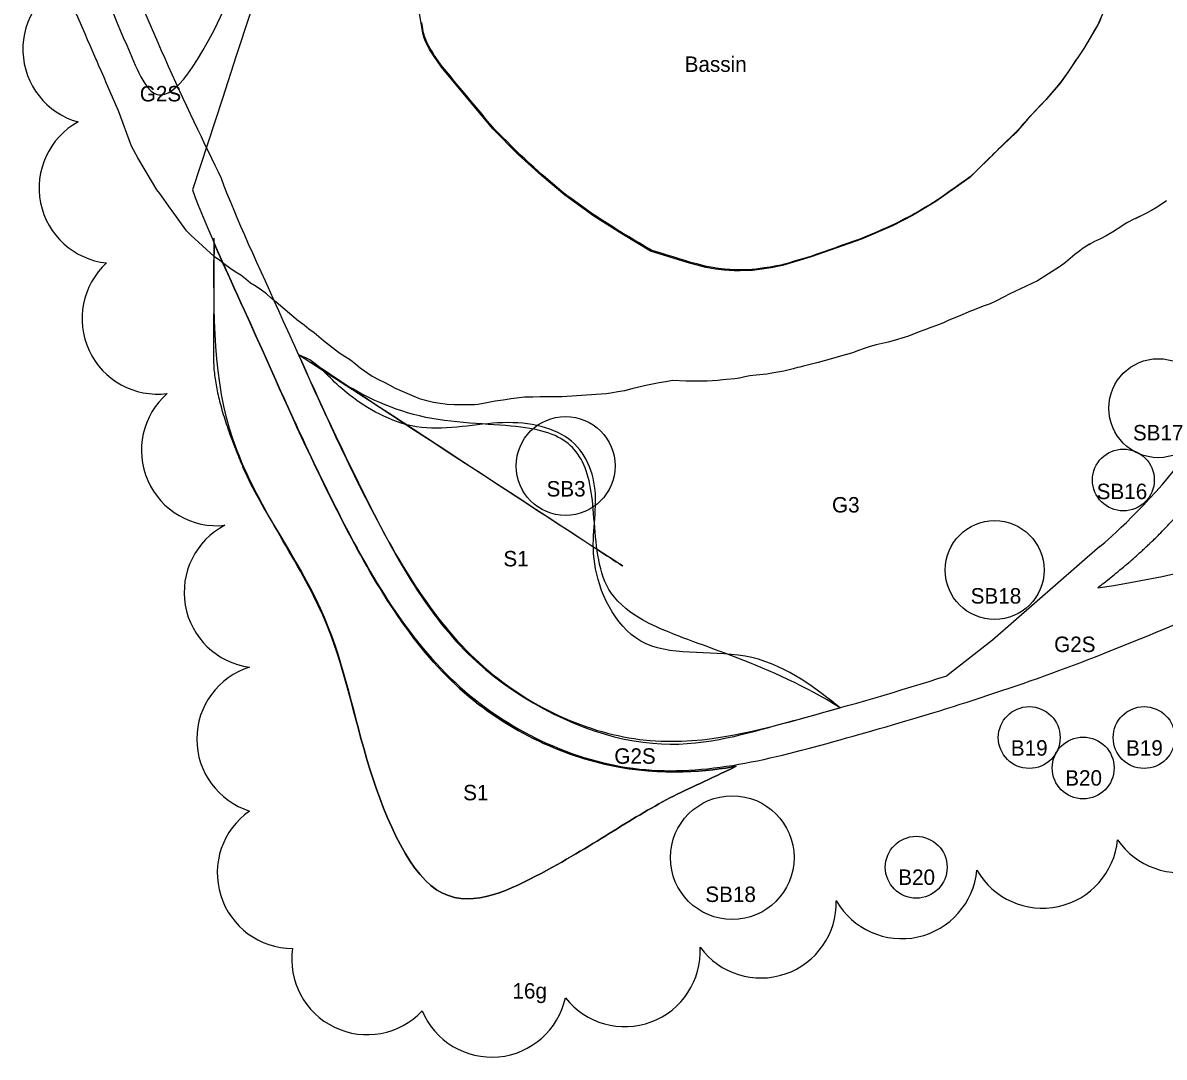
# Model space of a CAD drawing. Extents: x 0 to 512122, y 0 to 6212554.
# Drawn here: x 511409.2 to 511501.5, y 6211296 to 6211379.6 of the extents above; entities that cross this region are included whole.
import ezdxf

# ---------------------------------------------------------------- set-up
doc = ezdxf.new("R2010")
doc.units = 0
for name, color, linetype in [('_Paths', 7, 'Continuous'), ('_S1_rabarber', 7, 'Continuous'), ('Bassin - bottom', 7, 'Continuous'), ('Clouds', 7, 'Continuous'), ('TV_U_AFM_Symbl_Gul', 7, 'Continuous'), ('TV_U_LYS_Mastenummer', 7, 'Continuous'), ('TV_U_LYS_Nyx330-Trafiksti-x2', 7, 'Continuous')]:
    doc.layers.add(name, color=color, linetype=linetype)

msp = doc.modelspace()

# ---------------------------------------------------------------- linework, layer by layer
at = {"layer": '_Paths'}
msp.add_lwpolyline([(511496.345, 6211337.291), (511487.638, 6211329.704), (511483.951, 6211326.819)], dxfattribs=at)
msp.add_arc((511485.308, 6211411.031), 77.851, 278.00491, 309.13245, dxfattribs=at)
for points in [[(511450.039, 6211448.86), (511448.659, 6211442.81), (511441.758, 6211430.614), (511427.385, 6211422.182), (511415.868, 6211415.798), (511410.87, 6211405.413), (511411.537, 6211394.313), (511413.909, 6211386.762), (511418.057, 6211376.543), (511422.936, 6211366.106), (511450.039, 6211448.86), (511422.936, 6211366.106)], [(511452.493, 6211448.381), (511452.097, 6211446.356), (511450.738, 6211439.396), (511444.066, 6211426.759), (511429.553, 6211420.175), (511417.018, 6211415.504), (511412.404, 6211405.178), (511413.418, 6211395.795), (511416.522, 6211386.629), (511420.496, 6211376.909), (511423.945, 6211369.766), (511425.261, 6211367.041)], [(511496.284, 6211337.238), (511497.181, 6211337.983), (511503.211, 6211343.318), (511510.408, 6211356.244), (511526.967, 6211373.541), (511552.416, 6211374.723), (511569.62, 6211375.512), (511577.558, 6211375.876)], [(511496.15, 6211333.938), (511496.382, 6211334.119), (511496.614, 6211334.301), (511497.277, 6211334.827), (511497.707, 6211335.177), (511498.56, 6211335.891), (511498.983, 6211336.255), (511499.609, 6211336.816), (511499.816, 6211337.005), (511500.125, 6211337.293), (511500.227, 6211337.39), (511500.38, 6211337.535), (511500.431, 6211337.584), (511500.533, 6211337.682), (511500.583, 6211337.731), (511501.039, 6211338.174), (511501.432, 6211338.575), (511502.2, 6211339.389), (511502.574, 6211339.802), (511503.305, 6211340.639), (511503.662, 6211341.062), (511504.36, 6211341.916), (511504.702, 6211342.347), (511505.71, 6211343.65), (511506.356, 6211344.531), (511507.619, 6211346.304), (511508.235, 6211347.195), (511509.454, 6211348.976), (511510.058, 6211349.864), (511511.269, 6211351.627), (511511.876, 6211352.5), (511512.804, 6211353.79), (511513.115, 6211354.216), (511513.746, 6211355.061), (511514.065, 6211355.48), (511515.037, 6211356.725), (511515.702, 6211357.539), (511517.067, 6211359.122), (511517.767, 6211359.891), (511519.202, 6211361.371), (511519.937, 6211362.082), (511521.44, 6211363.435), (511522.209, 6211364.077), (511523.78, 6211365.279), (511524.583, 6211365.839), (511525.812, 6211366.612), (511526.226, 6211366.858), (511526.749, 6211367.15), (511526.853, 6211367.208), (511527.011, 6211367.293), (511527.064, 6211367.322), (511527.169, 6211367.378), (511527.222, 6211367.406), (511527.486, 6211367.545), (511527.7, 6211367.653), (511528.344, 6211367.971), (511528.781, 6211368.172), (511529.665, 6211368.555), (511530.114, 6211368.736), (511531.477, 6211369.251), (511532.41, 6211369.557), (511534.317, 6211370.104), (511535.292, 6211370.343), (511537.278, 6211370.766), (511538.289, 6211370.949), (511540.341, 6211371.267), (511541.381, 6211371.402), (511543.485, 6211371.635), (511544.548, 6211371.733), (511546.689, 6211371.901), (511547.767, 6211371.972), (511549.933, 6211372.096), (511551.02, 6211372.151), (511552.38, 6211372.215), (511552.652, 6211372.228), (511553.061, 6211372.247), (511553.197, 6211372.253), (511553.469, 6211372.266), (511553.605, 6211372.272), (511554.285, 6211372.304), (511555.913, 6211372.38), (511557.532, 6211372.455), (511560.757, 6211372.604), (511562.891, 6211372.704), (511566.075, 6211372.852), (511567.131, 6211372.901), (511568.185, 6211372.95)], [(511425.261, 6211367.041), (511426.423, 6211363.904), (511430.164, 6211355.897), (511436.319, 6211341.82), (511444.744, 6211326.863), (511459.39, 6211319.972), (511472.326, 6211323.351), (511480.124, 6211325.601), (511483.951, 6211326.819)], [(511422.936, 6211366.106), (511424.117, 6211362.932), (511427.915, 6211354.799), (511434.078, 6211340.703), (511442.957, 6211324.941), (511459.145, 6211317.324), (511475.029, 6211321.473), (511492.664, 6211326.687), (511505.824, 6211332.405), (511513.21, 6211335.68)]]:
    msp.add_open_spline(points, degree=3, dxfattribs=at)
at = {"layer": '_S1_rabarber'}
for points, degree in [([(511466.915, 6211319.511), (511464.697, 6211318.413), (511461.58, 6211317.119), (511456.737, 6211314.124), (511451.323, 6211310.773), (511442.088, 6211306.447), (511436.406, 6211320.592), (511434.43, 6211332.209), (511424.574, 6211345.595), (511424.646, 6211355.769), (511424.692, 6211362.215)], 3), ([(511424.689, 6211361.804), (511424.645, 6211355.496), (511424.652, 6211349.202), (511427.044, 6211343.62)], 2), ([(511424.689, 6211361.804), (511425.425, 6211360.117), (511428.531, 6211353.391), (511434.078, 6211340.703), (511442.957, 6211324.941), (511457.124, 6211318.275), (511464.776, 6211319.103), (511466.915, 6211319.511)], 3), ([(511466.915, 6211319.511), (511464.776, 6211319.103), (511457.124, 6211318.275), (511442.957, 6211324.941), (511434.078, 6211340.703), (511428.531, 6211353.391), (511425.425, 6211360.117), (511424.689, 6211361.804)], 3), ([(511475.316, 6211324.236), (511469.697, 6211327.763), (511457.957, 6211330.701), (511455.453, 6211335.54), (511455.453, 6211342.15), (511453.9, 6211345.823), (511449.929, 6211347.206), (511440.951, 6211347.206), (511434.131, 6211350.921), (511432.75, 6211352.217), (511431.512, 6211352.776), (511475.316, 6211324.236), (511431.512, 6211352.776)], 3), ([(511431.512, 6211352.776), (511433.015, 6211349.447), (511437.201, 6211340.255), (511444.745, 6211326.863), (511459.391, 6211319.971), (511469.457, 6211322.601), (511474.356, 6211323.965), (511475.316, 6211324.236)], 3), ([(511475.316, 6211324.236), (511473.557, 6211325.639), (511468.59, 6211329.599), (511458.65, 6211327.71), (511454.63, 6211335.987), (511456.066, 6211341.167), (511454.348, 6211346.436), (511448.167, 6211347.805), (511441.304, 6211346.051), (511435.366, 6211349.353), (511432.978, 6211352.237), (511431.944, 6211352.617), (511431.512, 6211352.776)], 3), ([(511431.512, 6211352.776), (511433.015, 6211349.447), (511437.201, 6211340.255), (511444.745, 6211326.863), (511459.391, 6211319.971), (511469.457, 6211322.601), (511474.356, 6211323.965), (511475.316, 6211324.236)], 3), ([(511427.044, 6211343.62), (511428.457, 6211340.321), (511434.43, 6211332.209), (511436.406, 6211320.592), (511442.088, 6211306.447), (511451.323, 6211310.773), (511456.737, 6211314.124), (511461.58, 6211317.119), (511464.697, 6211318.413), (511466.915, 6211319.511)], 3)]:
    msp.add_open_spline(points, degree=degree, dxfattribs=at)
at = {"layer": 'Bassin - bottom'}
msp.add_lwpolyline([(511497.036, 6211381.467), (511496.153, 6211379.46), (511495.031, 6211377.534), (511493.872, 6211375.818), (511493.14, 6211374.77), (511491.962, 6211373.383), (511490.531, 6211371.873), (511489.519, 6211370.719), (511488.027, 6211369.283), (511485.815, 6211367.1), (511483.052, 6211365.157), (511481.171, 6211364.036), (511479.554, 6211363.201), (511477.06, 6211362.117), (511472.976, 6211360.682), (511470.655, 6211359.988), (511469.755, 6211359.801), (511468.225, 6211359.601), (511467.226, 6211359.562), (511466.75, 6211359.562), (511465.946, 6211359.612), (511465.233, 6211359.699), (511464.45, 6211359.838), (511462.962, 6211360.229), (511459.99, 6211361.163), (511457.661, 6211362.549), (511455.393, 6211363.983), (511453.043, 6211365.671), (511451.184, 6211367.241), (511449.274, 6211368.974), (511447.234, 6211371.032), (511443.079, 6211376.016), (511442.477, 6211376.877), (511442.121, 6211377.457), (511441.834, 6211377.982), (511441.726, 6211378.244), (511441.648, 6211378.451), (511441.56, 6211378.805), (511441.157, 6211381.136)], dxfattribs=at)
at = {"layer": 'Clouds'}
for centre, radius, start, end in [((511415.323, 6211377.48), 6.1, 109.47776, 254.47776), ((511416.641, 6211366.262), 6.101, 118.92065, 263.92065), ((511420.11, 6211355.694), 6.1, 132.43503, 277.43503), ((511424.915, 6211345.053), 6.1, 131.15961, 276.15961), ((511428.37, 6211333.569), 6.1, 117.33555, 262.33555), ((511429.391, 6211321.706), 6.1, 107.5, 252.5), ((511502.794, 6211317.009), 6.1, 214.28131, 359.28131), ((511431.047, 6211310.885), 6.1, 124.89951, 269.89951), ((511491.679, 6211314.136), 6.1, 209.70863, 354.70863), ((511480.305, 6211311.67), 6.1, 209.76097, 354.76097), ((511468.912, 6211308.493), 6.1, 216.39722, 1.39722), ((511457.91, 6211304.553), 6.1, 218.00684, 3.00684), ((511437.073, 6211303.909), 6.1, 171.75121, 316.75121), ((511447.142, 6211302.09), 6.1, 202.76469, 347.76469)]:
    msp.add_arc(centre, radius, start, end, dxfattribs=at)
at = {"layer": 'TV_U_LYS_Mastenummer'}
for centre, radius in [((511501.05, 6211348.456), 4), ((511453.117, 6211343.786), 4), ((511498.228, 6211342.651), 2.5), ((511487.815, 6211335.372), 4), ((511490.611, 6211321.829), 2.5), ((511490.611, 6211321.829), 2.5), ((511499.901, 6211321.829), 2.5), ((511494.974, 6211319.369), 2.5), ((511494.974, 6211319.369), 2.5), ((511466.597, 6211312.12), 5), ((511466.597, 6211312.12), 5), ((511481.471, 6211311.344), 2.5), ((511481.471, 6211311.344), 2.5)]:
    msp.add_circle(centre, radius, dxfattribs=at)
at = {"layer": 'TV_U_LYS_Nyx330-Trafiksti-x2'}
for points in [[(511501.712, 6211365.222), (511501.049, 6211364.762), (511500.95, 6211364.706), (511500.509, 6211364.452), (511500.497, 6211364.446), (511500.029, 6211364.201), (511499.552, 6211363.964), (511499.199, 6211363.781), (511499.519, 6211363.947), (511499.199, 6211363.781), (511499.031, 6211363.71), (511499.009, 6211363.701), (511498.622, 6211363.5), (511498.557, 6211363.462), (511498.28, 6211363.298), (511498.19, 6211363.237), (511497.345, 6211362.679), (511497.291, 6211362.648), (511496.842, 6211362.394), (511496.374, 6211362.159), (511495.9, 6211361.93), (511495.455, 6211361.698), (511495.556, 6211361.755), (511495.494, 6211361.724), (511495.122, 6211361.483), (511494.965, 6211361.381), (511494.708, 6211361.19), (511494.304, 6211360.888), (511493.921, 6211360.564), (511493.54, 6211360.238), (511493.142, 6211359.93), (511493.065, 6211359.881), (511491.291, 6211358.749), (511490.832, 6211358.533), (511490.372, 6211358.317), (511489.912, 6211358.102), (511489.453, 6211357.886), (511488.996, 6211357.666), (511488.576, 6211357.452), (511487.903, 6211357.11), (511487.444, 6211356.904), (511486.968, 6211356.726), (511486.491, 6211356.55), (511486.019, 6211356.365), (511485.874, 6211356.302), (511485.049, 6211355.95), (511484.584, 6211355.76), (511484.123, 6211355.563), (511483.69, 6211355.362), (511483.116, 6211355.14), (511482.645, 6211354.97), (511482.174, 6211354.798), (511481.706, 6211354.621), (511481.24, 6211354.439), (511480.774, 6211354.257), (511480.59, 6211354.189), (511479.695, 6211353.924), (511479.207, 6211353.803), (511478.72, 6211353.683), (511478.231, 6211353.565), (511477.747, 6211353.433), (511477.268, 6211353.291), (511476.801, 6211353.111), (511476.332, 6211352.936), (511475.852, 6211352.794), (511475.828, 6211352.787), (511474.982, 6211352.558), (511474.502, 6211352.42), (511474.021, 6211352.282), (511473.537, 6211352.154), (511473.108, 6211352.031), (511472.364, 6211351.852), (511472.07, 6211351.783), (511471.877, 6211351.737), (511471.525, 6211351.631), (511470.771, 6211351.442), (511470.276, 6211351.37), (511469.784, 6211351.279), (511469.379, 6211351.215), (511468.523, 6211351.115), (511468.024, 6211351.064), (511467.618, 6211350.981), (511467.184, 6211350.893), (511466.799, 6211350.838), (511466.135, 6211350.781), (511465.846, 6211350.745), (511465.631, 6211350.718), (511465.439, 6211350.695), (511464.573, 6211350.646), (511464.16, 6211350.643), (511463.57, 6211350.637), (511463.063, 6211350.639), (511462.856, 6211350.639), (511461.772, 6211350.697), (511461.229, 6211350.599), (511460.686, 6211350.5), (511460.423, 6211350.452), (511459.601, 6211350.303), (511459.032, 6211350.162), (511458.462, 6211350.014), (511457.892, 6211349.868), (511457.338, 6211349.774), (511456.785, 6211349.681), (511456.388, 6211349.613), (511452.808, 6211349.368), (511452.225, 6211349.366), (511451.641, 6211349.363), (511451.058, 6211349.361), (511450.474, 6211349.359), (511449.891, 6211349.356), (511449.805, 6211349.345), (511448.712, 6211349.202), (511448.067, 6211349.118), (511447.423, 6211349.034), (511446.738, 6211348.886), (511446.057, 6211348.746), (511445.744, 6211348.72), (511444.121, 6211348.716), (511443.54, 6211348.764), (511443.383, 6211348.777), (511442.979, 6211348.84), (511442.425, 6211348.925), (511442.319, 6211348.942), (511441.899, 6211349.05), (511441.712, 6211349.099), (511441.384, 6211349.19), (511441.235, 6211349.231), (511439.362, 6211350.039), (511438.92, 6211350.291), (511438.469, 6211350.532), (511438.007, 6211350.76), (511437.542, 6211350.985), (511437.478, 6211351.029), (511436.503, 6211351.702), (511436.116, 6211352.019), (511435.728, 6211352.336), (511435.295, 6211352.603), (511434.865, 6211352.873), (511434.743, 6211352.972), (511433.54, 6211353.899), (511433.148, 6211354.214), (511432.772, 6211354.546), (511432.365, 6211354.847), (511431.973, 6211355.162), (511431.568, 6211355.464), (511431.526, 6211355.5), (511429.702, 6211357.029), (511429.319, 6211357.361), (511428.936, 6211357.693), (511428.534, 6211358.009), (511428.082, 6211358.283), (511427.646, 6211358.57), (511427.246, 6211358.888), (511426.841, 6211359.201), (511426.402, 6211359.486), (511425.962, 6211359.77), (511425.546, 6211360.075), (511425.144, 6211360.39), (511424.73, 6211360.696), (511424.697, 6211360.725), (511422.813, 6211362.432), (511422.466, 6211362.799), (511422.41, 6211362.876), (511421.291, 6211364.411), (511421.137, 6211364.639), (511420.291, 6211365.813), (511420.057, 6211366.11), (511418.598, 6211368.562), (511418.52, 6211368.699), (511418.005, 6211369.649), (511416.956, 6211372.504), (511416.858, 6211372.73), (511415.995, 6211374.719), (511415.79, 6211375.191), (511415.586, 6211375.663), (511415.381, 6211376.135), (511415.176, 6211376.607), (511415.132, 6211376.71), (511414.672, 6211377.77), (511414.466, 6211378.245), (511414.26, 6211378.721), (511414.054, 6211379.196), (511413.88, 6211379.596), (511413.572, 6211380.306)], [(511496.364, 6211379.901), (511496.203, 6211379.537), (511496.165, 6211379.472), (511496.152, 6211379.449), (511495.9, 6211379.017), (511495.648, 6211378.584), (511495.397, 6211378.152), (511495.346, 6211378.065), (511495.145, 6211377.72), (511495.081, 6211377.611), (511494.872, 6211377.302), (511494.593, 6211376.887), (511494.313, 6211376.473), (511494.033, 6211376.058), (511493.923, 6211375.895), (511493.749, 6211375.647), (511493.463, 6211375.237), (511493.202, 6211374.863), (511493.191, 6211374.847), (511493.175, 6211374.828), (511492.851, 6211374.447), (511492.528, 6211374.066), (511492.204, 6211373.685), (511492.013, 6211373.46), (511491.947, 6211373.391), (511491.872, 6211373.311), (511491.537, 6211372.958), (511491.528, 6211372.948), (511491.184, 6211372.586), (511490.84, 6211372.223), (511490.581, 6211371.95), (511490.5, 6211371.857), (511490.278, 6211371.604), (511490.17, 6211371.481), (511490.156, 6211371.464), (511489.888, 6211371.159), (511489.84, 6211371.105), (511489.639, 6211370.875), (511489.57, 6211370.796), (511489.548, 6211370.776), (511489.505, 6211370.734), (511489.145, 6211370.387), (511488.785, 6211370.04), (511488.425, 6211369.694), (511488.078, 6211369.36), (511488.065, 6211369.347), (511488.018, 6211369.3), (511487.709, 6211368.995), (511487.579, 6211368.867), (511487.353, 6211368.644), (511486.997, 6211368.293), (511486.641, 6211367.942), (511486.285, 6211367.591), (511485.929, 6211367.239), (511485.865, 6211367.177), (511485.53, 6211366.94), (511485.121, 6211366.653), (511484.712, 6211366.365), (511484.303, 6211366.077), (511483.894, 6211365.79), (511483.485, 6211365.502), (511483.103, 6211365.234), (511483.074, 6211365.217), (511482.645, 6211364.961), (511482.215, 6211364.705), (511481.786, 6211364.449), (511481.356, 6211364.193), (511481.221, 6211364.113), (511480.917, 6211363.955), (511480.472, 6211363.726), (511480.028, 6211363.497), (511479.605, 6211363.278), (511479.583, 6211363.269), (511479.124, 6211363.07), (511478.666, 6211362.87), (511478.207, 6211362.671), (511477.749, 6211362.472), (511477.29, 6211362.272), (511477.111, 6211362.194), (511476.824, 6211362.093), (511476.352, 6211361.928), (511475.88, 6211361.762), (511475.408, 6211361.596), (511474.937, 6211361.43), (511474.465, 6211361.264), (511473.993, 6211361.099), (511473.522, 6211360.933), (511473.05, 6211360.767), (511473.027, 6211360.759), (511472.571, 6211360.623), (511472.092, 6211360.48), (511471.613, 6211360.336), (511471.134, 6211360.193), (511470.706, 6211360.065), (511470.654, 6211360.054), (511470.359, 6211359.993), (511470.164, 6211359.952), (511469.806, 6211359.878), (511469.673, 6211359.86), (511469.177, 6211359.796), (511468.682, 6211359.731), (511468.276, 6211359.678), (511468.185, 6211359.674), (511467.686, 6211359.655), (511467.277, 6211359.639), (511467.186, 6211359.639), (511466.801, 6211359.639), (511466.686, 6211359.646), (511466.4, 6211359.664), (511466.187, 6211359.677), (511465.997, 6211359.689), (511465.69, 6211359.726), (511465.284, 6211359.776), (511465.194, 6211359.792), (511464.702, 6211359.88), (511464.501, 6211359.915), (511464.215, 6211359.99), (511463.731, 6211360.118), (511463.248, 6211360.245), (511463.013, 6211360.306), (511462.767, 6211360.384), (511462.29, 6211360.533), (511461.813, 6211360.683), (511461.336, 6211360.833), (511460.859, 6211360.983), (511460.382, 6211361.133), (511460.041, 6211361.24), (511459.919, 6211361.313), (511459.489, 6211361.568), (511459.059, 6211361.824), (511458.63, 6211362.08), (511458.2, 6211362.336), (511457.771, 6211362.592), (511457.712, 6211362.626), (511457.347, 6211362.857), (511456.924, 6211363.124), (511456.502, 6211363.392), (511456.079, 6211363.659), (511455.657, 6211363.926), (511455.444, 6211364.06), (511455.242, 6211364.206), (511454.836, 6211364.497), (511454.726, 6211364.576), (511454.43, 6211364.789), (511454.024, 6211365.08), (511453.946, 6211365.136), (511453.618, 6211365.372), (511453.471, 6211365.477), (511453.211, 6211365.664), (511453.093, 6211365.748), (511452.822, 6211365.977), (511452.44, 6211366.3), (511452.058, 6211366.622), (511451.676, 6211366.945), (511451.294, 6211367.268), (511451.235, 6211367.318), (511450.922, 6211367.601), (511450.552, 6211367.937), (511450.182, 6211368.273), (511449.811, 6211368.609), (511449.441, 6211368.945), (511449.325, 6211369.05), (511449.083, 6211369.294), (511448.731, 6211369.649), (511448.379, 6211370.005), (511448.028, 6211370.36), (511447.676, 6211370.715), (511447.324, 6211371.07), (511447.285, 6211371.109), (511447, 6211371.451), (511446.68, 6211371.835), (511446.36, 6211372.219), (511446.04, 6211372.603), (511445.719, 6211372.987), (511445.399, 6211373.371), (511445.079, 6211373.756), (511444.759, 6211374.14), (511444.439, 6211374.524), (511444.119, 6211374.908), (511443.798, 6211375.292), (511443.478, 6211375.676), (511443.158, 6211376.06), (511443.13, 6211376.093), (511442.868, 6211376.467), (511442.582, 6211376.877), (511442.528, 6211376.954), (511442.316, 6211377.3), (511442.172, 6211377.534), (511442.064, 6211377.732), (511441.885, 6211378.059), (511441.836, 6211378.176), (511441.776, 6211378.321), (511441.699, 6211378.528), (511441.669, 6211378.647), (511441.611, 6211378.882), (511441.567, 6211379.136), (511441.482, 6211379.628)]]:
    msp.add_lwpolyline(points, dxfattribs=at)

# ---------------------------------------------------------------- texts
at = {"layer": 'TV_U_AFM_Symbl_Gul'}
for s, p in [('Bassin', (511462.747, 6211375.644)), ('G2S', (511418.682, 6211373.256)), ('SB17', (511498.998, 6211345.85)), ('SB3', (511451.578, 6211341.315)), ('SB16', (511496.067, 6211341.103)), ('G3', (511474.663, 6211340.022)), ('S1', (511448.088, 6211335.666)), ('SB18', (511485.878, 6211332.659)), ('G2S', (511492.627, 6211328.74)), ('B19', (511489.127, 6211320.365)), ('B19', (511498.441, 6211320.365)), ('G2S', (511457.058, 6211319.71)), ('B20', (511493.523, 6211317.941)), ('S1', (511444.832, 6211316.755)), ('B20', (511480.021, 6211309.916)), ('SB18', (511464.42, 6211308.535)), ('16g', (511448.82, 6211300.725))]:
    msp.add_text(s, height=1.25, dxfattribs=at).set_placement(p)

doc.saveas('drawing.dxf')
